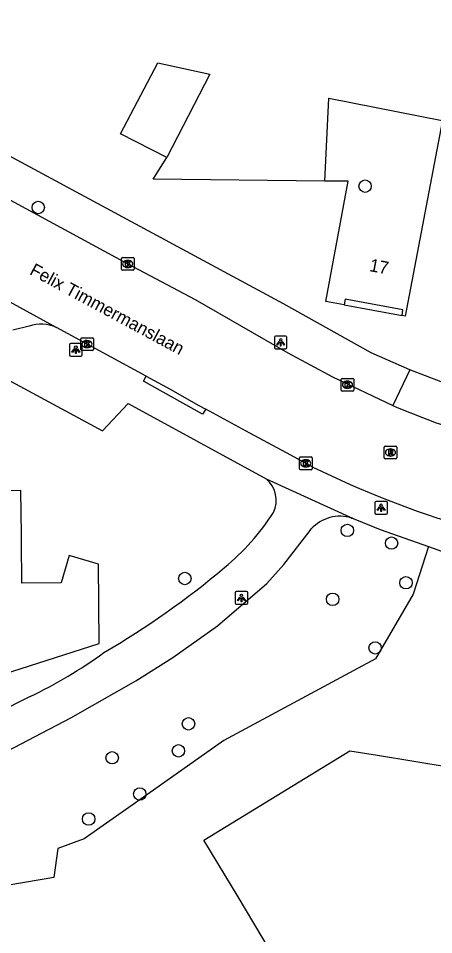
# Model space of a CAD drawing. Extents: x 161258 to 161838, y 380836 to 381727.
# Drawn here: x 161655.9 to 161688.7, y 381015 to 381087.2 of the extents above; entities that cross this region are included whole.
import ezdxf

# ---------------------------------------------------------------- set-up
doc = ezdxf.new("R2010")
doc.units = 0
for name, color, linetype in [('IMGEO_Boom', 7, 'Continuous'), ('IMGEO_Groenvoorziening', 7, 'Continuous'), ('IMGEO_Kolk', 7, 'Continuous'), ('IMGEO_Lichtpunt', 7, 'Continuous'), ('IMGEO_Muur', 7, 'Continuous'), ('IMGEO_Openbare_ruimte_label', 7, 'Continuous'), ('IMGEO_Pand', 7, 'Continuous'), ('IMGEO_Pand_nummerreeks', 7, 'Continuous'), ('IMGEO_Pand_overbouw', 7, 'Continuous'), ('IMGEO_Rijbaan_lokaal_open', 7, 'Continuous'), ('IMGEO_Rioolput', 7, 'Continuous'), ('IMGEO_Voetpad_open', 7, 'Continuous')]:
    doc.layers.add(name, color=color, linetype=linetype)

msp = doc.modelspace()

# ---------------------------------------------------------------- linework, layer by layer
at = {"layer": 'IMGEO_Boom'}
for centre in [(161683.262, 381073.968), (161657.506, 381072.291), (161681.865, 381046.857), (161685.347, 381045.858), (161669.054, 381043.067), (161686.481, 381042.736), (161680.709, 381041.429), (161684.05, 381037.604), (161669.348, 381031.621), (161668.551, 381029.497), (161663.33, 381028.949), (161665.505, 381026.097), (161661.482, 381024.125)]:
    msp.add_circle(centre, 0.489, dxfattribs=at)
at = {"layer": 'IMGEO_Groenvoorziening'}
msp.add_lwpolyline([(161688.26, 381045.583), (161687.06, 381041.825), (161684.086, 381036.733), (161672.137, 381030.317), (161666.141, 381026.08), (161661.136, 381022.555), (161659.038, 381021.802), (161658.733, 381019.525), (161644.202, 381017.041)], dxfattribs=at)
at = {"layer": 'IMGEO_Kolk'}
for p, q in [((161664.057, 381067.42), (161664.057, 381068.272)), ((161664.132, 381068.346), (161664.984, 381068.346)), ((161665.058, 381068.272), (161665.058, 381067.42)), ((161664.568, 381067.566), (161664.543, 381067.566)), ((161664.545, 381068.126), (161664.57, 381068.126)), ((161664.984, 381067.346), (161664.132, 381067.346)), ((161660.852, 381061.105), (161660.852, 381061.957)), ((161660.927, 381062.031), (161661.779, 381062.031)), ((161661.34, 381061.811), (161661.365, 381061.811)), ((161661.853, 381061.957), (161661.853, 381061.105)), ((161661.779, 381061.031), (161660.927, 381061.031)), ((161661.363, 381061.251), (161661.338, 381061.251)), ((161681.37, 381057.904), (161681.37, 381058.756)), ((161681.445, 381058.83), (161682.297, 381058.83)), ((161682.371, 381058.756), (161682.371, 381057.904)), ((161681.881, 381058.05), (161681.856, 381058.05)), ((161681.858, 381058.61), (161681.883, 381058.61)), ((161682.297, 381057.83), (161681.445, 381057.83)), ((161678.083, 381051.715), (161678.083, 381052.567)), ((161678.158, 381052.641), (161679.01, 381052.641)), ((161678.571, 381052.421), (161678.596, 381052.421)), ((161679.084, 381052.567), (161679.084, 381051.715)), ((161679.01, 381051.641), (161678.158, 381051.641)), ((161678.594, 381051.861), (161678.569, 381051.861))]:
    msp.add_line(p, q, dxfattribs=at)
for points in [[(161664.057, 381067.42), (161664.057, 381068.272)], [(161664.132, 381068.346), (161664.984, 381068.346)], [(161665.058, 381068.272), (161665.058, 381067.42)], [(161664.378, 381068.046), (161664.501, 381068.046), (161664.501, 381067.895), (161664.631, 381068.046), (161664.795, 381068.046), (161664.649, 381067.895), (161664.802, 381067.646), (161664.65, 381067.646), (161664.565, 381067.81), (161664.501, 381067.743), (161664.501, 381067.646), (161664.378, 381067.646), (161664.378, 381068.046)], [(161664.984, 381067.346), (161664.132, 381067.346)], [(161660.852, 381061.105), (161660.852, 381061.957)], [(161660.927, 381062.031), (161661.779, 381062.031)], [(161661.173, 381061.731), (161661.296, 381061.731), (161661.296, 381061.58), (161661.426, 381061.731), (161661.59, 381061.731), (161661.444, 381061.58), (161661.597, 381061.331), (161661.445, 381061.331), (161661.36, 381061.495), (161661.296, 381061.428), (161661.296, 381061.331), (161661.173, 381061.331), (161661.173, 381061.731)], [(161661.853, 381061.957), (161661.853, 381061.105)], [(161661.779, 381061.031), (161660.927, 381061.031)], [(161681.37, 381057.904), (161681.37, 381058.756)], [(161681.445, 381058.83), (161682.297, 381058.83)], [(161682.371, 381058.756), (161682.371, 381057.904)], [(161681.691, 381058.53), (161681.814, 381058.53), (161681.814, 381058.379), (161681.944, 381058.53), (161682.108, 381058.53), (161681.962, 381058.379), (161682.115, 381058.13), (161681.963, 381058.13), (161681.878, 381058.294), (161681.814, 381058.227), (161681.814, 381058.13), (161681.691, 381058.13), (161681.691, 381058.53)], [(161682.297, 381057.83), (161681.445, 381057.83)], [(161678.083, 381051.715), (161678.083, 381052.567)], [(161678.158, 381052.641), (161679.01, 381052.641)], [(161678.404, 381052.341), (161678.527, 381052.341), (161678.527, 381052.19), (161678.657, 381052.341), (161678.821, 381052.341), (161678.675, 381052.19), (161678.828, 381051.941), (161678.676, 381051.941), (161678.591, 381052.105), (161678.527, 381052.038), (161678.527, 381051.941), (161678.404, 381051.941), (161678.404, 381052.341)], [(161679.084, 381052.567), (161679.084, 381051.715)], [(161679.01, 381051.641), (161678.158, 381051.641)]]:
    msp.add_lwpolyline(points, dxfattribs=at)
for centre, start, end in [((161664.134, 381068.27), 91.55205, 178.44795), ((161664.134, 381068.27), 91.55205, 178.44795), ((161664.982, 381068.27), 1.55205, 88.44795), ((161664.982, 381068.27), 1.55205, 88.44795), ((161664.134, 381067.422), 181.55205, 268.44795), ((161664.134, 381067.422), 181.55205, 268.44795), ((161664.982, 381067.422), 271.55205, 358.44795), ((161664.982, 381067.422), 271.55205, 358.44795), ((161660.929, 381061.955), 91.55205, 178.44795), ((161660.929, 381061.955), 91.55205, 178.44795), ((161661.777, 381061.955), 1.55205, 88.44795), ((161661.777, 381061.955), 1.55205, 88.44795), ((161660.929, 381061.107), 181.55205, 268.44795), ((161660.929, 381061.107), 181.55205, 268.44795), ((161661.777, 381061.107), 271.55205, 358.44795), ((161661.777, 381061.107), 271.55205, 358.44795), ((161681.447, 381058.754), 91.55205, 178.44795), ((161681.447, 381058.754), 91.55205, 178.44795), ((161682.295, 381058.754), 1.55205, 88.44795), ((161682.295, 381058.754), 1.55205, 88.44795), ((161681.447, 381057.906), 181.55205, 268.44795), ((161681.447, 381057.906), 181.55205, 268.44795), ((161682.295, 381057.906), 271.55205, 358.44795), ((161682.295, 381057.906), 271.55205, 358.44795), ((161678.16, 381052.565), 91.55205, 178.44795), ((161678.16, 381052.565), 91.55205, 178.44795), ((161679.008, 381052.565), 1.55205, 88.44795), ((161679.008, 381052.565), 1.55205, 88.44795), ((161678.16, 381051.717), 181.55205, 268.44795), ((161678.16, 381051.717), 181.55205, 268.44795), ((161679.008, 381051.717), 271.55205, 358.44795), ((161679.008, 381051.717), 271.55205, 358.44795)]:
    msp.add_arc(centre, 0.0765, start, end, dxfattribs=at)
for centre, major_axis, ratio, start_param, end_param in [((161664.544, 381067.846), (-0.387, 0.002), 0.722429, 4.712389, 7.853982), ((161664.569, 381067.846), (-0.39, 0.002), 0.717154, 1.570796, 4.712389), ((161661.339, 381061.531), (-0.387, 0.002), 0.722429, 4.712389, 7.853982), ((161661.364, 381061.531), (-0.39, 0.002), 0.717154, 1.570796, 4.712389), ((161681.857, 381058.33), (-0.387, 0.002), 0.722429, 4.712389, 7.853982), ((161681.882, 381058.33), (-0.39, 0.002), 0.717154, 1.570796, 4.712389), ((161678.57, 381052.141), (-0.387, 0.002), 0.722429, 4.712389, 7.853982), ((161678.595, 381052.141), (-0.39, 0.002), 0.717154, 1.570796, 4.712389)]:
    msp.add_ellipse(centre, major_axis=major_axis, ratio=ratio, start_param=start_param, end_param=end_param, dxfattribs=at)
at = {"layer": 'IMGEO_Lichtpunt'}
for p, q in [((161676.11, 381062.064), (161676.11, 381061.257)), ((161676.11, 381062.064), (161676.11, 381061.257)), ((161677.012, 381062.159), (161676.204, 381062.159)), ((161677.012, 381062.159), (161676.204, 381062.159)), ((161677.106, 381061.257), (161677.106, 381062.064)), ((161677.106, 381061.257), (161677.106, 381062.064)), ((161659.969, 381061.492), (161659.969, 381060.685)), ((161659.969, 381061.492), (161659.969, 381060.685)), ((161660.871, 381061.587), (161660.063, 381061.587)), ((161660.871, 381061.587), (161660.063, 381061.587)), ((161660.965, 381060.685), (161660.965, 381061.492)), ((161660.965, 381060.685), (161660.965, 381061.492)), ((161676.204, 381061.163), (161677.012, 381061.163)), ((161676.204, 381061.163), (161677.012, 381061.163)), ((161660.063, 381060.591), (161660.871, 381060.591)), ((161660.063, 381060.591), (161660.871, 381060.591)), ((161684.02, 381049.04), (161684.02, 381048.233)), ((161684.02, 381049.04), (161684.02, 381048.233)), ((161684.922, 381049.135), (161684.114, 381049.135)), ((161684.922, 381049.135), (161684.114, 381049.135)), ((161685.016, 381048.233), (161685.016, 381049.04)), ((161685.016, 381048.233), (161685.016, 381049.04)), ((161684.114, 381048.139), (161684.922, 381048.139)), ((161684.114, 381048.139), (161684.922, 381048.139)), ((161673.015, 381041.942), (161673.015, 381041.135)), ((161673.015, 381041.942), (161673.015, 381041.135)), ((161673.917, 381042.037), (161673.109, 381042.037)), ((161673.917, 381042.037), (161673.109, 381042.037)), ((161674.011, 381041.135), (161674.011, 381041.942)), ((161674.011, 381041.135), (161674.011, 381041.942)), ((161673.109, 381041.041), (161673.917, 381041.041)), ((161673.109, 381041.041), (161673.917, 381041.041))]:
    msp.add_line(p, q, dxfattribs=at)
for points in [[(161676.484, 381061.728), (161676.523, 381061.7), (161676.335, 381061.438), (161676.297, 381061.465), (161676.484, 381061.728)], [(161676.586, 381061.68), (161676.633, 381061.68), (161676.633, 381061.358), (161676.586, 381061.358), (161676.586, 381061.68)], [(161676.696, 381061.7), (161676.734, 381061.727), (161676.921, 381061.465), (161676.882, 381061.437), (161676.696, 381061.7)], [(161660.343, 381061.156), (161660.382, 381061.128), (161660.194, 381060.866), (161660.156, 381060.893), (161660.343, 381061.156)], [(161660.445, 381061.108), (161660.492, 381061.108), (161660.492, 381060.786), (161660.445, 381060.786), (161660.445, 381061.108)], [(161660.555, 381061.128), (161660.593, 381061.155), (161660.78, 381060.893), (161660.741, 381060.865), (161660.555, 381061.128)], [(161684.394, 381048.704), (161684.433, 381048.676), (161684.245, 381048.414), (161684.207, 381048.441), (161684.394, 381048.704)], [(161684.496, 381048.656), (161684.543, 381048.656), (161684.543, 381048.334), (161684.496, 381048.334), (161684.496, 381048.656)], [(161684.606, 381048.676), (161684.644, 381048.703), (161684.831, 381048.441), (161684.792, 381048.413), (161684.606, 381048.676)], [(161673.389, 381041.606), (161673.428, 381041.578), (161673.24, 381041.316), (161673.202, 381041.343), (161673.389, 381041.606)], [(161673.491, 381041.558), (161673.538, 381041.558), (161673.538, 381041.236), (161673.491, 381041.236), (161673.491, 381041.558)], [(161673.601, 381041.578), (161673.639, 381041.605), (161673.826, 381041.343), (161673.787, 381041.315), (161673.601, 381041.578)]]:
    msp.add_lwpolyline(points, dxfattribs=at)
for centre in [(161676.609, 381061.862), (161660.468, 381061.29), (161684.519, 381048.838), (161673.514, 381041.74)]:
    msp.add_circle(centre, 0.0994, dxfattribs=at)
for centre, start, end in [((161676.204, 381062.064), 90, 180), ((161676.204, 381062.064), 90, 180), ((161677.012, 381062.064), 0, 90), ((161677.012, 381062.064), 0, 90), ((161660.063, 381061.492), 90, 180), ((161660.063, 381061.492), 90, 180), ((161660.871, 381061.492), 0, 90), ((161660.871, 381061.492), 0, 90), ((161676.204, 381061.257), 180, 270), ((161676.204, 381061.257), 180, 270), ((161677.012, 381061.257), 270, 0), ((161677.012, 381061.257), 270, 360), ((161660.063, 381060.685), 180, 270), ((161660.063, 381060.685), 180, 270), ((161660.871, 381060.685), 270, 0), ((161660.871, 381060.685), 270, 360), ((161684.114, 381049.04), 90, 180), ((161684.114, 381049.04), 90, 180), ((161684.922, 381049.04), 0, 90), ((161684.922, 381049.04), 0, 90), ((161684.114, 381048.233), 180, 270), ((161684.114, 381048.233), 180, 270), ((161684.922, 381048.233), 270, 0), ((161684.922, 381048.233), 270, 360), ((161673.109, 381041.942), 90, 180), ((161673.109, 381041.942), 90, 180), ((161673.917, 381041.942), 0, 90), ((161673.917, 381041.942), 0, 90), ((161673.109, 381041.135), 180, 270), ((161673.109, 381041.135), 180, 270), ((161673.917, 381041.135), 270, 0), ((161673.917, 381041.135), 270, 360)]:
    msp.add_arc(centre, 0.0946, start, end, dxfattribs=at)
at = {"layer": 'IMGEO_Muur'}
msp.add_lwpolyline([(161680.083, 381074.372), (161666.561, 381074.513), (161667.643, 381076.236)], dxfattribs=at)
at = {"layer": 'IMGEO_Pand'}
for points in [[(161671.017, 381082.791), (161667.643, 381076.236), (161663.997, 381078.093), (161666.916, 381083.685), (161671.017, 381082.791)], [(161689.325, 381079.031), (161686.406, 381063.731), (161686.171, 381063.778), (161686.239, 381064.217), (161681.697, 381065.06), (161681.611, 381064.618), (161680.177, 381064.899), (161681.925, 381074.353), (161680.083, 381074.372), (161680.401, 381080.903), (161689.346, 381079.153)], [(161649.92, 381033.973), (161662.306, 381037.947), (161662.244, 381044.197), (161659.932, 381044.868), (161659.311, 381042.727), (161656.211, 381042.689), (161656.179, 381045.966), (161656.174, 381046.518), (161656.14, 381049.999), (161642.958, 381049.862)], [(161694.83, 381010.743), (161677.189, 381013.689), (161675.934, 381013.514), (161675.817, 381013.709), (161673.249, 381017.994), (161670.565, 381022.473), (161682.071, 381029.5), (161684.247, 381029.146), (161692.838, 381027.747), (161696.159, 381027.212), (161697.502, 381026.996), (161694.83, 381010.743)]]:
    msp.add_lwpolyline(points, dxfattribs=at)
at = {"layer": 'IMGEO_Pand_overbouw'}
msp.add_lwpolyline([(161686.171, 381063.778), (161686.239, 381064.217), (161681.697, 381065.06), (161681.611, 381064.618)], close=True, dxfattribs=at)
at = {"layer": 'IMGEO_Rijbaan_lokaal_open'}
for points in [[(161635.58, 381083.294), (161638.009, 381081.966), (161651.628, 381074.813), (161654.689, 381073.206), (161664.516, 381067.867), (161669.88, 381065.045), (161677.177, 381060.856), (161680.698, 381058.941), (161685.459, 381056.689)], [(161632.244, 381076.986), (161634.807, 381075.723), (161638.895, 381073.701), (161645.436, 381070.252), (161658.944, 381062.836)], [(161666.013, 381059.008), (161658.944, 381062.836)], [(161666.013, 381059.008), (161667.897, 381057.988), (161670.17, 381056.699), (161670.707, 381056.408)], [(161679.132, 381051.841), (161677.079, 381052.97), (161674.187, 381054.522), (161670.707, 381056.408)]]:
    msp.add_lwpolyline(points, dxfattribs=at)
for centre, radius, start, end in [((161712.678, 381120.499), 69.373, 246.89865, 251.63862), ((161713.742, 381122.865), 79.008, 244.02026, 253.45591)]:
    msp.add_arc(centre, radius, start, end, dxfattribs=at)
at = {"layer": 'IMGEO_Rioolput'}
for p, q in [((161684.766, 381052.571), (161684.766, 381053.423)), ((161684.841, 381053.497), (161685.693, 381053.497)), ((161685.254, 381053.277), (161685.279, 381053.277)), ((161685.767, 381053.423), (161685.767, 381052.571)), ((161685.693, 381052.497), (161684.841, 381052.497)), ((161685.277, 381052.717), (161685.252, 381052.717))]:
    msp.add_line(p, q, dxfattribs=at)
for points in [[(161684.766, 381052.571), (161684.766, 381053.423)], [(161684.841, 381053.497), (161685.693, 381053.497)], [(161685.355, 381053.195), (161685.103, 381053.197), (161685.103, 381052.797)], [(161685.281, 381053.116), (161685.227, 381053.116), (161685.227, 381053.035)], [(161685.227, 381053.035), (161685.279, 381053.035)], [(161685.767, 381053.423), (161685.767, 381052.571)], [(161685.693, 381052.497), (161684.841, 381052.497)], [(161685.103, 381052.797), (161685.227, 381052.797), (161685.227, 381052.959), (161685.238, 381052.959)], [(161685.285, 381052.93), (161685.356, 381052.797), (161685.496, 381052.797), (161685.431, 381052.923)]]:
    msp.add_lwpolyline(points, dxfattribs=at)
for centre, radius, start, end in [((161684.843, 381053.421), 0.0765, 91.55205, 178.44795), ((161684.843, 381053.421), 0.0765, 91.55205, 178.44795), ((161685.263, 381053.224), 0.19, 274.7715, 282.96867), ((161685.287, 381053.02), 0.0964, 77.00612, 93.18647), ((161685.301, 381053.077), 0.0378, 276.66336, 79.67722), ((161685.354, 381053.085), 0.109, 350.36119, 89.41601), ((161685.352, 381053.085), 0.112, 277.58423, 350.98172), ((161685.336, 381052.87), 0.108, 29.51342, 73.79051), ((161685.691, 381053.421), 0.0765, 1.55205, 88.44795), ((161685.691, 381053.421), 0.0765, 1.55205, 88.44795), ((161684.843, 381052.573), 0.0765, 181.55205, 268.44795), ((161684.843, 381052.573), 0.0765, 181.55205, 268.44795), ((161685.237, 381052.906), 0.0533, 26.02933, 88.69889), ((161685.691, 381052.573), 0.0765, 271.55205, 358.44795), ((161685.691, 381052.573), 0.0765, 271.55205, 358.44795)]:
    msp.add_arc(centre, radius, start, end, dxfattribs=at)
for centre, major_axis, ratio, start_param, end_param in [((161685.253, 381052.997), (-0.387, 0.002), 0.722429, 4.712389, 7.853982), ((161685.278, 381052.997), (-0.39, 0.002), 0.717154, 1.570796, 4.712389)]:
    msp.add_ellipse(centre, major_axis=major_axis, ratio=ratio, start_param=start_param, end_param=end_param, dxfattribs=at)
at = {"layer": 'IMGEO_Voetpad_open'}
for points in [[(161686.794, 381059.495), (161683.729, 381060.833), (161676.825, 381064.703), (161608.252, 381101.703), (161603.367, 381104.463), (161599.292, 381107.15)], [(161631.294, 381071.59), (161662.556, 381054.709), (161664.588, 381056.855), (161675.471, 381050.931)], [(161656.781, 381062.954), (161655.5, 381062.629)], [(161686.794, 381059.495), (161685.459, 381056.689)], [(161691.724, 381057.608), (161686.794, 381059.495)], [(161670.707, 381056.408), (161670.449, 381056.006), (161665.804, 381058.621), (161666.013, 381059.008)], [(161675.471, 381050.931), (161682.316, 381047.794)], [(161682.202, 381047.832), (161682.259, 381047.814), (161682.316, 381047.794)], [(161682.316, 381047.794), (161684.449, 381046.924), (161688.26, 381045.583)], [(161640.355, 381022.779), (161653.332, 381028.579), (161660.071, 381032.09), (161665.195, 381035.022), (161668.104, 381036.84), (161671.619, 381039.336), (161675.516, 381042.671), (161676.868, 381044.169), (161678.939, 381046.842), (161679.02, 381046.972)], [(161688.26, 381045.583), (161691.047, 381044.602), (161693.931, 381043.708), (161696.121, 381043.204), (161710.784, 381040.897)], [(161656.876, 381033.773), (161651.548, 381031.097), (161639.35, 381025.737), (161622.189, 381019.011), (161621.073, 381018.632)]]:
    msp.add_lwpolyline(points, dxfattribs=at)
for centre, radius, start, end in [((161657.721, 381060.295), 2.82, 64.28966, 109.46512), ((161674.041, 381049.231), 2.221, 333.98502, 49.91753), ((161659.779, 381058.837), 19.397, 309.77174, 326.9464), ((161681.286, 381044.906), 3.066, 72.61314, 137.63487), ((161627.818, 381096.86), 69.069, 300.31453, 309.97147), ((161639.753, 381069.076), 39.236, 295.87499, 305.75591)]:
    msp.add_arc(centre, radius, start, end, dxfattribs=at)

# ---------------------------------------------------------------- texts
at = {"layer": 'IMGEO_Openbare_ruimte_label'}
msp.add_text('Felix Timmermanslaan', height=1, rotation=331.64104, dxfattribs=at).set_placement((161656.756, 381067.066))
at = {"layer": 'IMGEO_Pand_nummerreeks'}
msp.add_text('17', height=1, rotation=349.53009, dxfattribs=at).set_placement((161683.553, 381067.286))

doc.saveas('drawing.dxf')
